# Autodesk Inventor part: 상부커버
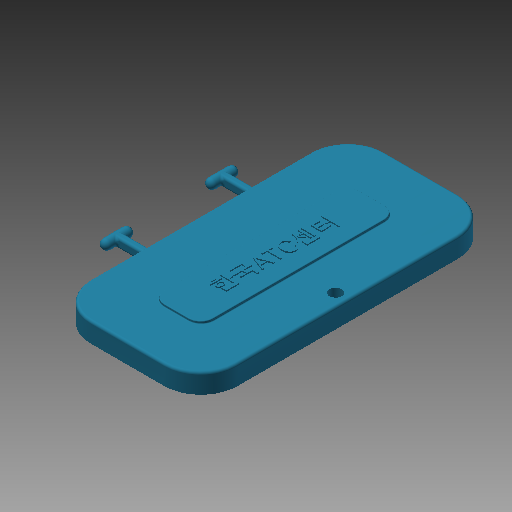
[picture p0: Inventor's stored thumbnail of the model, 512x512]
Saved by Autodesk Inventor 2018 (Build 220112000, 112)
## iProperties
Created: 2016-02
Part Number: 상부커버
Material: ABS 플라스틱
Document SubType Name: Modeling
Designer: mduedu
Density: 2.71 g/cm^3
Mass: 42.0587 g
Surface Area: 149.263 cm^2
Volume: 15.5198 cm^3
Appearance: 터키옥색
Author: mduedu
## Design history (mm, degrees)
sketch "스케치1"
  geometry: L1 (30, 60)-(-30, 60); L2 (-30, 60)-(-30, -60); L3 (-30, -60)-(30, -60); L4 (30, -60)-(30, 60); L5 (30, 60)-(-30, -60); L6 (-30, 60)-(30, -60); 1 further point
  constraints: 12 end point, 2 midpoint, 2 parallel, 1 horizontal, 1 perpendicular
  dimensions: "d0" = 60 distance of L2.end L3.end; "d2" = 120 distance of L1.end L2.end
extrude "돌출1" new body sketch "스케치1" distance "d3" = 8; taper "d4" = 0 deg
fillet "모깎기1" dims "d5" = 15
node "작업 평면1"
sketch "스케치7"
  geometry: L1 (-39, 4)-(129, 4) reference; L2 (65, 2)-(68, 2); L3 (68, 2)-(68, 6); L4 (68, 6)-(65, 6); L5 (65, 6)-(65, 2); L6 (65, 2)-(68, 6); L7 (68, 2)-(65, 6); 2 further points
  constraints: 12 end point, 2 midpoint, 2 parallel, 1 horizontal, 1 perpendicular, 1 point on line
  dimensions: "d33" = 4 distance of L2.end L3.end; "d35" = 3 distance of L3.end L4.end; "d36" = 20 distance from line of L5 point (45, 0)
extrude "돌출3" join sketch "스케치7" distance "d37" = 15; taper "d38" = 0 deg
fillet "모깎기6" dims "d39" = 2
node "작업 평면3"
sketch "스케치8"
  geometry: A1 r 2 centre (-13, 2) between (-13, 4) and (-13, 0) reference; 2 further points
  constraints: 1 coincident, 1 vertical alignment, 2 other
extrude "돌출4" join sketch "스케치8" stored distance "d40" = 12; taper "d41" = 0 deg
fillet "모깎기7" dims "d42" = 2
fillet "모깎기8" dims "d43" = 1
fillet "모깎기9" dims "d44" = 1
sketch "스케치2"
  geometry: L1 (30, 45)-(30, -45) reference; L2 (15, -60)-(-15, -60) reference; L3 (-30, -45)-(-30, 45) reference; L4 (-15, 60)-(15, 60) reference; L5 (25, 45)-(25, -45); L6 (15, -55)-(-15, -55); L7 (-25, -45)-(-25, 45); L8 (-15, 55)-(15, 55); A1 r 15 centre (15, 45) between (30, 45) and (15, 60) reference; A2 r 15 centre (15, -45) between (15, -60) and (30, -45) reference; A3 r 15 centre (-15, -45) between (-30, -45) and (-15, -60) reference; A4 r 15 centre (-15, 45) between (-15, 60) and (-30, 45) reference; A5 r 10 centre (15, 45) between (25, 45) and (15, 55); A6 r 10 centre (15, -45) between (15, -55) and (25, -45); A7 r 10 centre (-15, -45) between (-25, -45) and (-15, -55); A8 r 10 centre (-15, 45) between (-15, 55) and (-25, 45); 4 further points
  constraints: 8 end point, 8 point on circle, 4 centre point, 4 midpoint, 7 other
  dimensions: "d8" = 5 distance between parallel lines of L7 L3
hole "구멍1" sketch "스케치2" at (25, 0) diameter "d9" = 5; stored, may be unused: countersink angle "d13" = 90 deg, drill point angle "d15" = 118 deg; dims "d10" = 6, "d11" = 4, "d12" = 2, "d14" = 8
sketch "스케치3"
  geometry: L1 (10, -40)-(-10, -40); L2 (-10, -40)-(-10, 40); L3 (-10, 40)-(10, 40); L4 (10, 40)-(10, -40); L5 (10, -40)-(-10, 40); L6 (-10, -40)-(10, 40); 1 further point
  constraints: 12 end point, 2 midpoint, 2 parallel, 1 horizontal, 1 perpendicular
  dimensions: "d16" = 80 distance of L1.end L2.end; "d18" = 20 distance of L2.end L3.end
extrude "돌출2" join sketch "스케치3" distance "d19" = 1; taper "d20" = 0 deg
fillet "모깎기2" dims "d21" = 5
fillet "모깎기3" dims "d22" = 0.3
sketch "스케치4"
  geometry: 2 further points
  constraints: 1 coincident, 1 other
feature "엠보싱1" sketch "스케치4" dims "d8" = 5, "d24" = 0.5, "d25" = 0
fillet "모깎기10" dims "d45" = 1
node "솔리드1"
mirror "대칭1"
node "절단 모서리 투영1"
